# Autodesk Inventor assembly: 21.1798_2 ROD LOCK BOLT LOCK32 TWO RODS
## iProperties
Created: 2007-03
Part Number: 21.1798_2 ROD LOCK BOLT LOCK32 TWO RODS
Document SubType Name: Assembly
Designer: Andy Moles
Author: Andy Moles
